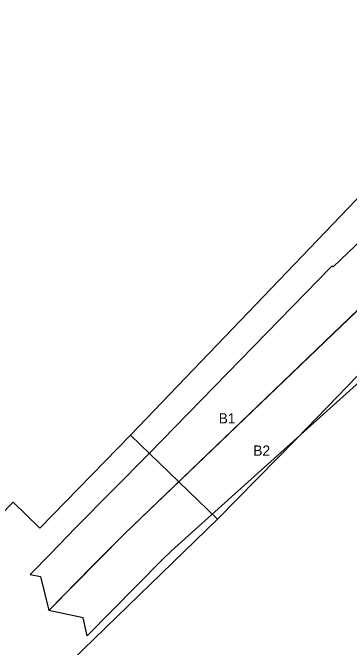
# Model space of a CAD drawing. Extents: x 2253035 to 2279930, y 13774972 to 13793443.
# Drawn here: x 2254975.6 to 2255239.2, y 13790856.5 to 13791353.4 of the extents above; entities that cross this region are included whole.
import ezdxf

# ---------------------------------------------------------------- set-up
doc = ezdxf.new("R2010")
doc.units = 0
for name, color, linetype in [('E_Utility_ATT_Fiber', 7, 'Continuous'), ('E_Utility_Gas_Gas Line_GL_Elevation', 7, 'Continuous'), ('E_Utility_Water_Water Valve_WV_Elevation', 7, 'Continuous')]:
    doc.layers.add(name, color=color, linetype=linetype)

msp = doc.modelspace()

# ---------------------------------------------------------------- linework, layer by layer
at = {"layer": 'E_Utility_ATT_Fiber'}
for p, q in [((2255225.35, 13791154.69), (2255082.51, 13791008.27)), ((2255225.88, 13791155.18), (2255225.35, 13791154.69)), ((2255062.92, 13790944.99), (2255252.37, 13791126.93)), ((2255082.51, 13791008.27), (2255025.19, 13790950.23)), ((2255025.19, 13790950.23), (2255005.21, 13790929.64)), ((2255003.84, 13790885.26), (2255062.92, 13790944.99)), ((2255005.21, 13790929.64), (2254989.39, 13790913.45)), ((2254989.39, 13790913.45), (2254997.43, 13790911.95)), ((2254997.43, 13790911.95), (2255003.84, 13790885.26))]:
    msp.add_line(p, q, dxfattribs=at)
msp.add_lwpolyline([(2255249.13, 13791176.15), (2255226.58, 13791154.5), (2255225.88, 13791155.18)], dxfattribs=at)
msp.add_lwpolyline([(2255310.9, 13791139.84), (2255307.22, 13791115.83), (2255295.13, 13791104.21), (2255289.23, 13791098.55), (2255284.2, 13791093.71), (2255282.12, 13791095.87), (2255262.79, 13791078.49), (2255121.12, 13790951.06), (2255099.87, 13790931.94), (2255092.37, 13790924.75), (2255033.91, 13790865.37), (2255030.7, 13790879.5), (2255003.84, 13790885.26), (2255037.34, 13790919.6), (2255062.92, 13790944.99), (2255252.37, 13791126.93), (2255264.21, 13791138.47)], close=True, dxfattribs=at)
at = {"layer": 'E_Utility_Water_Water Valve_WV_Elevation'}
for points in [[(2255623, 13791457.45), (2255517, 13791344.43), (2255472.8, 13791295.19), (2255379.75, 13791207.78), (2255198.17, 13791020.02), (2255136.03, 13790956.76), (2255067.98, 13791022.64), (2255178.24, 13791137.81), (2255292.07, 13791256.47), (2255389.41, 13791303.46), (2255390.98, 13791330.06), (2255459.85, 13791397.22)], [(2254546.81, 13790460.49), (2254568.33, 13790481.91), (2254507.04, 13790536.95), (2254843.77, 13790880.73), (2254898.27, 13790830.54), (2254918.63, 13790852.86), (2254887.7, 13790879.96), (2254975.9, 13790970.16), (2254996.81, 13790949.66), (2255067.98, 13791022.64), (2255136.03, 13790956.76), (2254978.02, 13790803.63), (2254955.49, 13790780.79), (2254337.57, 13790152.53)]]:
    msp.add_lwpolyline(points, dxfattribs=at)

# ---------------------------------------------------------------- texts
at = {"layer": 'E_Utility_Gas_Gas Line_GL_Elevation'}
for s, p in [('B1', (2255136.94, 13791031.78)), ('B2', (2255164.05, 13791006.53))]:
    msp.add_text(s, height=8, dxfattribs=at).set_placement(p)

doc.saveas('drawing.dxf')
